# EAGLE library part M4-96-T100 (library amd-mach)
AMD MACH SERIES
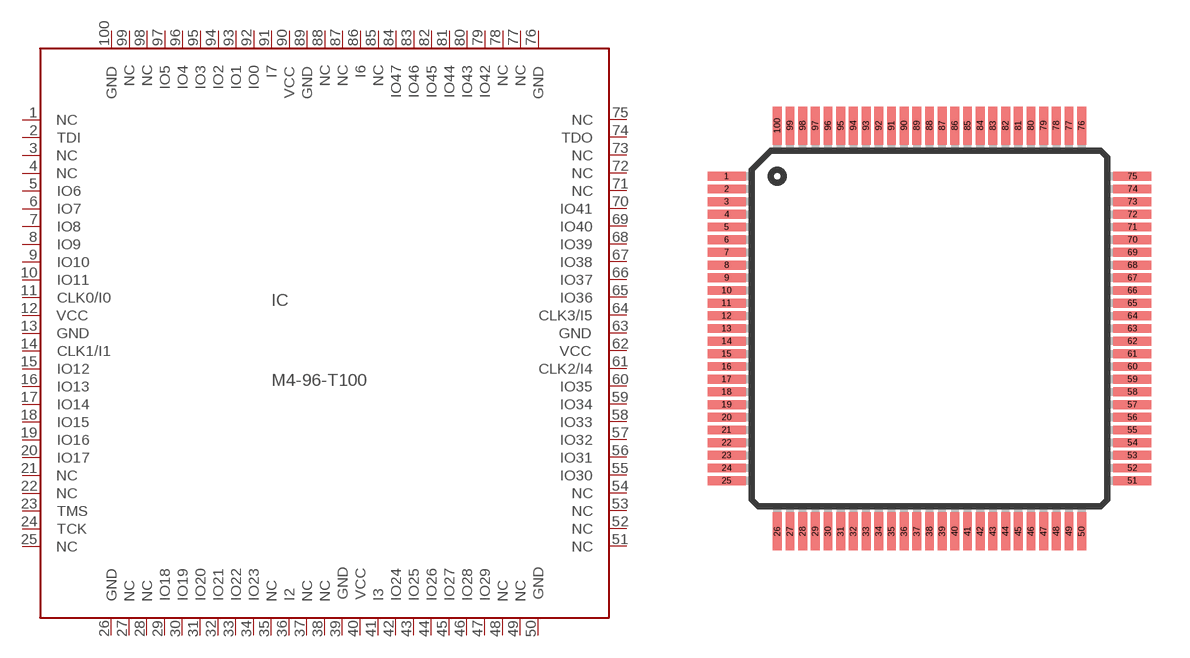
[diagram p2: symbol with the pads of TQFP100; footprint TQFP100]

Designator prefix IC

## M4-96-T100 (OC_FARNELL: unknown; OC_NEWARK: unknown)  [TQFP100]
1  NC1  nc
2  TDI  in
3  NC2  nc
4  NC3  nc
5  IO6
6  IO7
7  IO8
8  IO9
9  IO10
10  IO11
11  CLK0/I0  in
12  VCC  pwr
13  GND  pwr
14  CLK1/I1  in
15  IO12
16  IO13
17  IO14
18  IO15
19  IO16
20  IO17
21  NC4  nc
22  NC5  nc
23  TMS  in
24  TCK  in
25  NC6  nc
26  GND  pwr
27  NC7  nc
28  NC8  nc
29  IO18
30  IO19
31  IO20
32  IO21
33  IO22
34  IO23
35  NC9  nc
36  I2  in
37  NC10  nc
38  NC11  nc
39  GND  pwr
40  VCC  pwr
41  I3  in
42  IO24
43  IO25
44  IO26
45  IO27
46  IO28
47  IO29
48  NC12  nc
49  NC13  nc
50  GND  pwr
51  NC14  nc
52  NC15  nc
53  NC18  nc
54  NC19  nc
55  IO30
56  IO31
57  IO32
58  IO33
59  IO34
60  IO35
61  CLK2/I4  in
62  VCC  pwr
63  GND  pwr
64  CLK3/I5  in
65  IO36
66  IO37
67  IO38
68  IO39
69  IO40
70  IO41
71  NC20  nc
72  NC21  nc
73  NC22  nc
74  TDO  out
75  NC23  nc
76  GND  pwr
77  NC24  nc
78  NC25  nc
79  IO42
80  IO43
81  IO44
82  IO45
83  IO46
84  IO47
85  NC26  nc
86  I6  in
87  NC27  nc
88  NC28  nc
89  GND  pwr
90  VCC  pwr
91  I7  in
92  IO0
93  IO1
94  IO2
95  IO3
96  IO4
97  IO5
98  NC29  nc
99  NC30  nc
100  GND  pwr

## Footprint TQFP100 (pad centres in mm)
THIN QUAD FLAT PACK
smd 1.5 x 0.35: 1 -8,6; 2 -8,5.5; 3 -8,5; 4 -8,4.5; 5 -8,4; 6 -8,3.5; 7 -8,3; 8 -8,2.5; 9 -8,2; 10 -8,1.5; 11 -8,1; 12 -8,0.5; 13 -8,0; 14 -8,-0.5; 15 -8,-1; 16 -8,-1.5; 17 -8,-2; 18 -8,-2.5; 19 -8,-3; 20 -8,-3.5; 21 -8,-4; 22 -8,-4.5; 23 -8,-5; 24 -8,-5.5; 25 -8,-6; 51 8,-6; 52 8,-5.5; 53 8,-5; 54 8,-4.5; 55 8,-4; 56 8,-3.5; 57 8,-3; 58 8,-2.5; 59 8,-2; 60 8,-1.5; 61 8,-1; 62 8,-0.5; 63 8,0; 64 8,0.5; 65 8,1; 66 8,1.5; 67 8,2; 68 8,2.5; 69 8,3; 70 8,3.5; 71 8,4; 72 8,4.5; 73 8,5; 74 8,5.5; 75 8,6
smd 0.35 x 1.5: 26 -6,-8; 27 -5.5,-8; 28 -5,-8; 29 -4.5,-8; 30 -4,-8; 31 -3.5,-8; 32 -3,-8; 33 -2.5,-8; 34 -2,-8; 35 -1.5,-8; 36 -1,-8; 37 -0.5,-8; 38 0,-8; 39 0.5,-8; 40 1,-8; 41 1.5,-8; 42 2,-8; 43 2.5,-8; 44 3,-8; 45 3.5,-8; 46 4,-8; 47 4.5,-8; 48 5,-8; 49 5.5,-8; 50 6,-8; 76 6,8; 77 5.5,8; 78 5,8; 79 4.5,8; 80 4,8; 81 3.5,8; 82 3,8; 83 2.5,8; 84 2,8; 85 1.5,8; 86 1,8; 87 0.5,8; 88 0,8; 89 -0.5,8; 90 -1,8; 91 -1.5,8; 92 -2,8; 93 -2.5,8; 94 -3,8; 95 -3.5,8; 96 -4,8; 97 -4.5,8; 98 -5,8; 99 -5.5,8; 100 -6,8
